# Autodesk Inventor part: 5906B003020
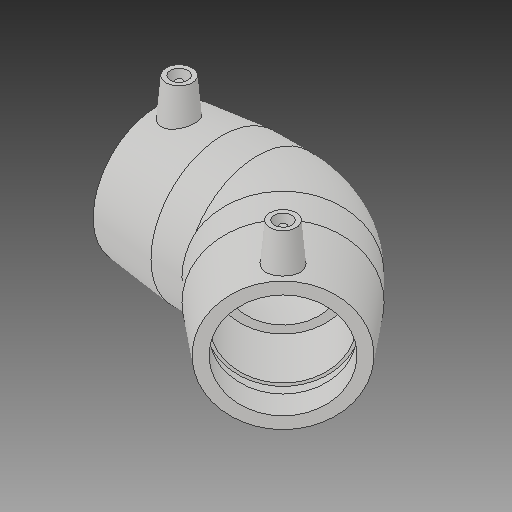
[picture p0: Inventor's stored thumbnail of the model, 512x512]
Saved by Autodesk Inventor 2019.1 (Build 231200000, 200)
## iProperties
Created: 2017-06
Part Number: 5906B003020
Material: Generic
Description: PLASSON 45° ELBOW 2''
Document SubType Name: Modeling
Designer: KIM
Mass: 55.0731 g
Surface Area: 148.067 cm^2
Volume: 55.0731 cm^3
Density: 1 g/cm^3
Appearance: Default
Author: KIM
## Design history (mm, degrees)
derived "5906B.ipt"
feature "Solid1::5906B.ipt"
tag "TaggingFeature1"
body "Solid1"
other parameters: "d_" = 60.1, "L_" = 149.098, "L_1" = 57.404, "D_" = 82.042, "A_" = 58.42, "d_2" = 12, "d2" = 82.042, "d4" = 37.2745, "d5" = 73.8378, "d8" = 168 deg, "d10" = 22.9616, "d11" = 7.65387, "d14" = 17.6296, "d18" = 60.1, "d19" = 3.52592, "d20" = 168 deg, "d22" = 75.47864, "d23" = 82.042, "d24" = 73.21428, "d29" = 58.42, "d30" = 15, "d31" = 59.6392, "d34" = 5 deg, "d35" = 12, "d39" = 0, "d41" = 4, "d42" = 14, "d43" = 0, "d44" = 9.6, "d45" = 4.8, "d46" = 6, "d47" = 0, "d49" = 60.1, "d50" = 51.085, "d51" = 22.9616, "d52" = 57.404, "d54" = 135 deg, "d65" = 60.1, "d67" = 45 deg, "d71" = 135 deg, "d75" = 4.1021, "d82" = 45 deg, "d83" = 57.404, "d84" = 73.8378, "d86" = 36.9189, "d87" = 135 deg, "d88" = 149.098, "d90" = 57.404, "d91" = 0, "d92" = 57.404, "d93" = 0, "d94" = 135 deg, "d95" = 36.60714, "d98" = 149.098, "d99" = 44.7294, "d101" = 3, "d102" = 0, "d103" = 3, "d104" = 0, "d105" = 16.64716, "d106" = 4.16179
